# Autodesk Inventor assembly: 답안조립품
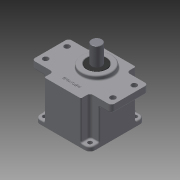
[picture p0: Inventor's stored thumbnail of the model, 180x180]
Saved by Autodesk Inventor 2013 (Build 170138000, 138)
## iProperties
Created: 2015-07
Part Number: 답안조립품
Document SubType Name: Assembly
Designer: user
Author: user
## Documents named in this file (12)
- C:\Users\user\Desktop\450734V1006\답안조립품.iam
- C:\Users\user\Desktop\450734V1006\서브축.ipt
- C:\Users\user\Desktop\450734V1006\베어링 6003.ipt
- 베어링 6003.ipt
- C:\Users\user\Desktop\450734V1006\베어링 608.ipt
- 베어링 608.ipt
- C:\Users\user\Desktop\450734V1006\메인축.ipt
- C:\Users\user\Desktop\450734V1006\본체.ipt
- C:\Users\user\Desktop\450734V1006\커버.ipt
- C:\Users\user\Desktop\450734V1006\오일실 8x22x7.ipt
- C:\Users\user\Desktop\450734V1006\오일실 17x32x8.ipt
- C:\Users\user\Desktop\450734V1006\M4x0.5x16.ipt
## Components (4 placed, 1 different names)
1. M4x0.5x12:1
2. M4x0.5x12:2
3. M4x0.5x12:3
4. M4x0.5x12:4
